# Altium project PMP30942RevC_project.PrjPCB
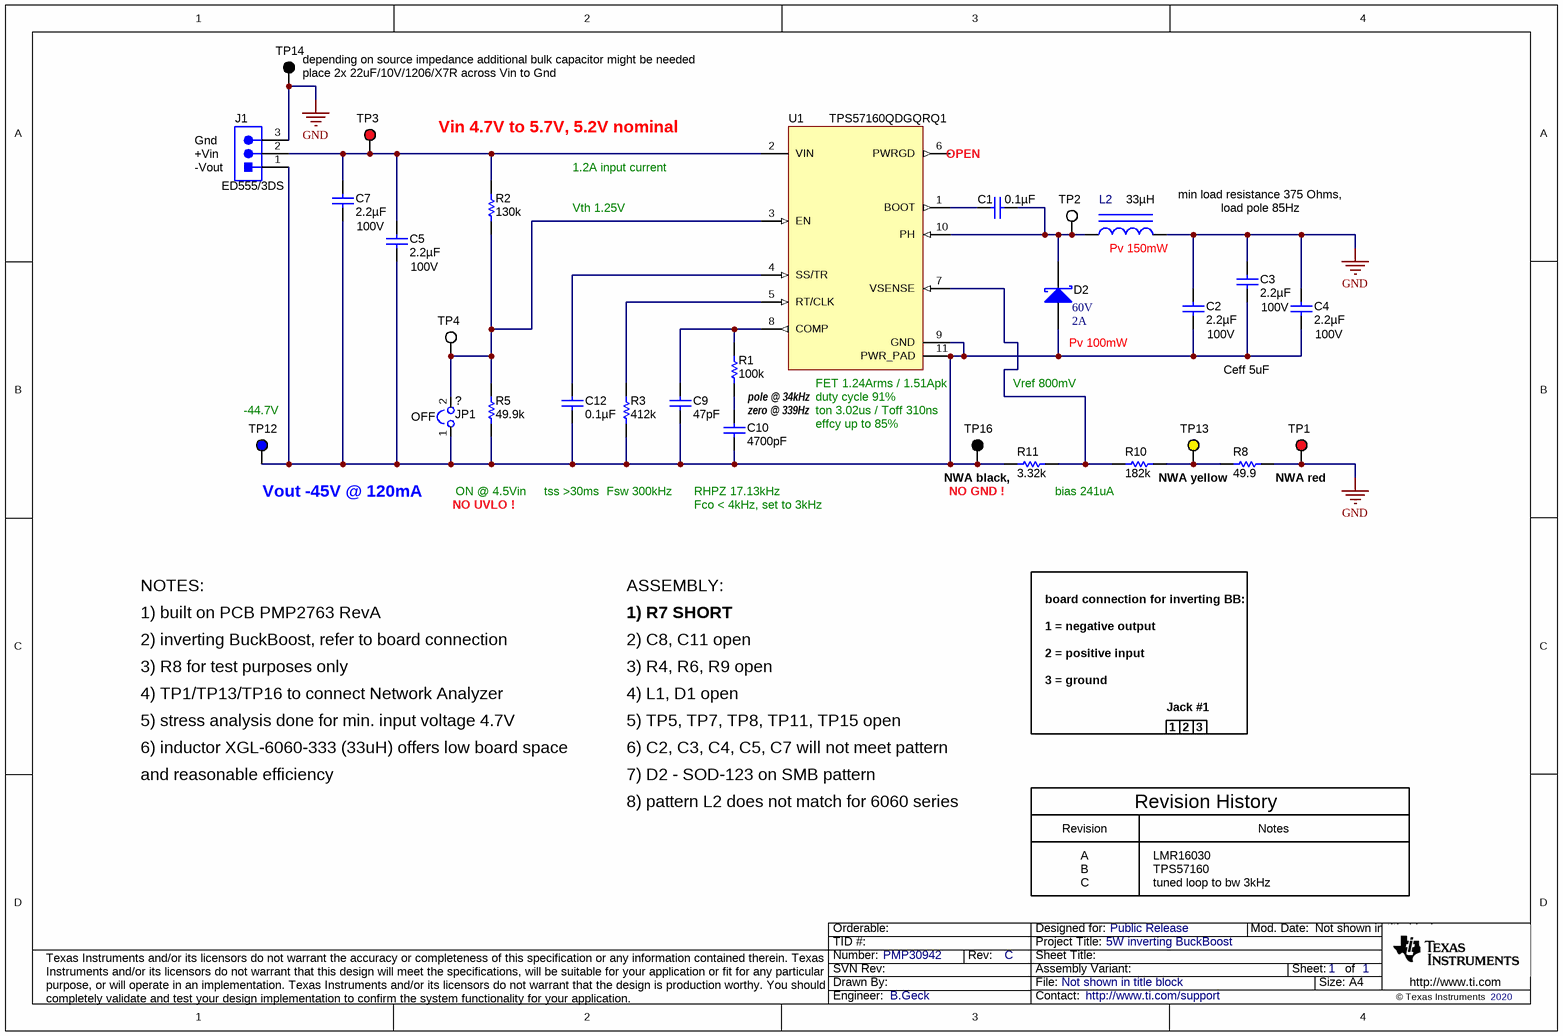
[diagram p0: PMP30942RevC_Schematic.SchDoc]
CopyrightYear: 2020; PCB_Layout: B.Geck; PCB_Rev: A; PRJ_Customer: Public Release; PRJ_Engineer: B.Geck; PRJ_Number: PMP30942; PRJ_Title: 5W inverting BuckBoost; SCH_Rev: C; TechSupport: http://www.ti.com/support
1 sheet, 29 parts. Net scope: global (net labels, ports and power ports of the same name join across sheets).
Board file: PMP2763_REV_A_board.PcbDoc

## Sheet PMP30942RevC_Schematic.SchDoc
size A4; Date: Not shown in title block; ApprovedBy: Not shown in title block; CheckedBy: Not shown in title block; Author: Not shown in title block; CompanyName: Not shown in title block; Engineer: Not shown in title block; Organization: Not shown in title block; Address1: Not shown in title block; Address2: Not shown in title block; Address3: Not shown in title block; Address4: Not shown in title block; DocumentNumber: 1; Revision: Use project parameter SCH_Rev; SheetNumber: 1; SheetTotal: 1; PageSetup: Record=PageOptions¦CenterHorizontal=True¦CenterVertical=True¦PrintScale=0.70¦XCorrection=1.00¦YCorrection=1.00¦PrintKind=0¦BorderSize=5000000¦LeftOffset=0¦BottomOffset=0¦Orientation=2¦PaperLength=1000¦PaperWidth=1000¦Scale=100¦PaperSource=15¦PrintQuality=600¦MediaType=1¦DitherType=10¦PaperKind=A4¦PrintScaleMode=1

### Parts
?  JP1  [JMP-600_035MIL]
C1  ValueDisplayed: 0.1µF  [0603]  (hidden comment: GRM188R71E104KA01D)
C2  ValueDisplayed: 2.2µF  Value2: 100V  [1206_190]  (hidden comment: GRM31CR72A225KA73L)
C3  ValueDisplayed: 2.2µF  Value2: 100V  [1206_190]  (hidden comment: GRM31CR72A225KA73L)
C4  ValueDisplayed: 2.2µF  Value2: 100V  [1206_190]  (hidden comment: GRM31CR72A225KA73L)
C5  ValueDisplayed: 2.2µF  Value2: 100V  [1206_190]  (hidden comment: GRM31CR72A225KA73L)
C7  ValueDisplayed: 2.2µF  Value2: 100V  [1206_190]  (hidden comment: GRM31CR72A225KA73L)
C9  ValueDisplayed: 47pF  [0603]  (hidden comment: GRM1885C1H470JA01D)
C10  ValueDisplayed: 4700pF  [0603]  (hidden comment: GRM188R71E472KA01D)
C12  ValueDisplayed: 0.1µF  [0603]  (hidden comment: GRM188R71E104KA01D)
D2  value 60V  Value1: 2A  [SOD-123W]  (hidden comment: PMEG6020ER,115)
J1  ED555/3DS  [TERM_BLK_ED555-3DS]
L2  ValueDisplayed: 33µH  [XAL6060]  (hidden comment: XAL6060-333MEB)
R1  ValueDisplayed: 100k  [0603]  (hidden comment: CRCW0603100KFKEA)
R2  ValueDisplayed: 130k  [0603]  (hidden comment: CRCW0603130KFKEA)
R3  ValueDisplayed: 412k  [0603]  (hidden comment: CRCW0603412KFKEA)
R5  ValueDisplayed: 49.9k  [0603]  (hidden comment: CRCW060349K9FKEA)
R8  ValueDisplayed: 49.9  [0603]  (hidden comment: CRCW060349R9FKEA)
R10  ValueDisplayed: 182k  [0603]  (hidden comment: CRCW0603182KFKEA)
R11  ValueDisplayed: 3.32k  [0603]  (hidden comment: CRCW06033K32FKEA)
TP1  5000  [Keystone5000]  (value not drawn)
TP2  5002  [Keystone5002]  (value not drawn)
TP3  5000  [Keystone5000]  (value not drawn)
TP4  5002  [Keystone5002]  (value not drawn)
TP12  5117  [Keystone5117]  (value not drawn)
TP13  5004  [Keystone5004]  (value not drawn)
TP14  5001  [Keystone5001]  (value not drawn)
TP16  5001  [Keystone5001]  (value not drawn)
U1  TPS57160QDGQRQ1  [DGQ0010D_N]

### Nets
GND: C2.1 C3.1 C4.1 J1.3 L2.2 R8.2 TP1.1 TP14.1
Net?_1: ?.1 C2.2 C3.2 C4.2 C5.2 C7.2 C9.2 C10.2 C12.2 D2.2(A) J1.1 R3.1 R5.1 R11.1 TP12.1 TP16.1 U1.9(GND) U1.11(PWR_PAD)
Net?_2: ?.2 R2.1 R5.2 TP4.1 U1.3(EN)
NetC1_1: C1.1 U1.1(BOOT)
NetC1_2: C1.2 D2.1(K) L2.1 TP2.1 U1.10(PH)
NetC5_1: C5.1 C7.1 J1.2 R2.2 TP3.1 U1.2(VIN)
NetC9_1: C9.1 R1.2 U1.8(COMP)
NetC10_1: C10.1 R1.1
NetC12_1: C12.1 U1.4(SS/TR)
NetR3_2: R3.2 U1.5(RT/CLK)
NetR8_1: R8.1 R10.2 TP13.1
NetR10_1: R10.1 R11.2 U1.7(VSENSE)

Not connected (* = marked no-connect by the designer): U1 6(PWRGD)

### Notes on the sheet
- (near TP14) place 2x 22uF/10V/1206/X7R across Vin to Gnd
- (near TP14) depending on source impedance additional bulk capacitor might be needed
- (near J1) Gnd
- (near J1) +Vin
- (near J1) -Vout
- Vin 4.7V to 5.7V, 5.2V nominal
- 1.2A input current
- (near U1) OPEN
- Vth 1.25V
- (near L2) Pv 150mW
- (near L2) min load resistance 375 Ohms,
- load pole 85Hz
- (near U1) FET 1.24Arms / 1.51Apk
- Vref 800mV
- (near D2) Pv 100mW
- Ceff 5uF
- (near TP12) -44.7V
- (near ?) OFF
- pole @ 34kHz
- zero @ 339Hz
- (near U1) duty cycle 91%
- ton 3.02us / Toff 310ns
- effcy up to 85%
- (near TP12) Vout -45V @ 120mA
- NO UVLO !
- ON @ 4.5Vin
- tss >30ms
- Fsw 300kHz
- (near C10) RHPZ 17.13kHz
- Fco < 4kHz, set to 3kHz
- NO GND !
- NWA black,
- bias 241uA
- NWA yellow
- NWA red
- NOTES:
- ASSEMBLY:
- 1) built on PCB PMP2763 RevA
- 2) inverting BuckBoost, refer to board connection
- 2) C8, C11 open
- 1) R7 SHORT
- board connection for inverting BB:
- 1 = negative output
- 2 = positive input
- 3) R8 for test purposes only
- 4) TP1/TP13/TP16 to connect Network Analyzer
- 5) stress analysis done for min. input voltage 4.7V
- 4) L1, D1 open
- 3) R4, R6, R9 open
- 5) TP5, TP7, TP8, TP11, TP15 open
- 3 = ground
- Jack #1
- 6) inductor XGL-6060-333 (33uH) offers low board space
- and reasonable efficiency
- 6) C2, C3, C4, C5, C7 will not meet pattern
- 7) D2 - SOD-123 on SMB pattern
- 1
- 2
- 3
- 8) pattern L2 does not match for 6060 series
- Revision
- A
- LMR16030
- Revision History
- Notes
- B
- C
- TPS57160
- tuned loop to bw 3kHz

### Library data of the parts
? = JMP-600_035MIL: Jumper,  0.600 inch length, PVC Insulation, AWG 22,; Manufacturer: 3M; PartNumber: 923345-06-C; area: 70000; Value: 923345-06-C
C1 C12 = GRM188R71E104KA01D: CAP, CERM, 0.1 µF, 25 V, +/- 10%, X7R, 0603; Manufacturer: MuRata; Polarized: N; CompType: Capacitor; Value: 0.1uF; U/M: EA; Cap_F: 0.0000001; Tolerance_%: 10; Value1: Unknown; VDC_V: 25; Value2: 25V; TaMin_C: -55; TaMax_C: 125
C2-C5 C7 = GRM31CR72A225KA73L: CAP, CERM, 2.2 µF, 100 V,+/- 10%, X7R, 1206; Manufacturer: MuRata; Polarized: N; CompType: Capacitor; Value: 2.2uF; U/M: EA; Cap_F: 0.0000022; Tolerance_%: 10; VDC_V: 100; TaMin_C: -55; TaMax_C: 125; Cap_Case: 1206; SizeArea_mm2: 5.12; SizeAreaWB_mm2: 10.92; SizeX_mm: 3.2; SizeY_mm: 1.6; SizeZ_mm: 1.9; AEC Category: Q200; Green_Lifecycle: Active; Green_REACh: Passed
C9 = GRM1885C1H470JA01D: CAP, CERM, 47 pF, 50 V,+/- 5%, C0G/NP0, 0603; Manufacturer: MuRata; Polarized: N; CompType: Capacitor; Value: 47pF; U/M: EA; Cap_F: 0.000000000047; Tolerance_%: 5; VDC_V: 50; Value2: 50V; TaMin_C: -55; TaMax_C: 125; SizeArea_mm2: 1.28; SizeAreaWB_mm2: 4.68; SizeX_mm: 1.6; SizeY_mm: 0.8; SizeZ_mm: 1; AEC Category: Q200; Green_Lifecycle: Active; Green_REACh: Passed
C10 = GRM188R71E472KA01D: CAP, CERM, 4700 pF, 25 V,+/- 10%, X7R, 0603; Manufacturer: MuRata; Polarized: N; CompType: Capacitor; Value: 4700pF; U/M: EA; Cap_F: 0.0000000047; Tolerance_%: 10; VDC_V: 25; Value2: 25V; TaMin_C: -55; TaMax_C: 125; SizeArea_mm2: 1.28; SizeAreaWB_mm2: 4.68; SizeX_mm: 1.6; SizeY_mm: 0.8; SizeZ_mm: 1; AEC Category: Q200
D2 = PMEG6020ER,115: Diode, Schottky, 60 V, 2 A, SOD-123W; Manufacturer: Nexperia; U/M: EA; Vf_V: 0.53; Value2: 0.53V; Io_A: 2; Vr_V: 60; TJmax_C: 150; SizeAreaWB_mm2: 12.15; SizeArea_mm2: 5.95; SizeX_mm: 3.5; SizeY_mm: 1.7; SizeZ_mm: 1; AEC Category: Q101; Green_Lifecycle: Not Set; Green_REACh: Incomplete
J1 = ED555/3DS: Terminal Block, 6A, 3.5mm Pitch, 3-Pos, TH; Manufacturer: On-Shore Technology; SymbolCreator: a0799628; CompType: Connector; U/M: EA
L2 = CMP-0085398-2: Inductor, Shielded, Composite, 33 µH, 3.6 A, 0.105 ohm, AEC-Q200 Grade 1, SMD; Manufacturer: Coilcraft; Isat: 3.7A @ 30% inductance drop; AEC Qualified: Y; Green_Lifecycle: Not Set; SizeX_mm: 6.36; SizeAreaWB_mm2: 71.5616; AEC Category: Q200; Value: 33uH; SizeY_mm: 6.56; AEC Grade: 1; SizeZ_mm: 6.1; Green_REACh: Incomplete; DCR_ohm: 0.105; Value2: 3.6A; Irms: 3.6A @ 40C rise; SizeArea_mm2: 41.7216
R1 = CRCW0603100KFKEA: RES, 100 k, 1%, 0.1 W, 0603; Manufacturer: Vishay-Dale; CompType: Resistor; Value: 100k; Res_ohm: 100000; Tolerance_%: 1; Power_W: 0.1; Value2: 0.1W; VDC_V: 75; TempCo: 100 ppm/C; SizeArea_mm2: 1.28; SizeX_mm: 1.6; SizeY_mm: 0.8; EIA_Code: E96; U/M: EA; AEC Category: Q200; Green_Lifecycle: Active; Green_REACh: Passed
R2 = CRCW0603130KFKEA: RES, 130 k, 1%, 0.1 W, 0603; Manufacturer: Vishay-Dale; CompType: Resistor; Value: 130k; Res_ohm: 130000; Tolerance_%: 1; Power_W: 0.1; Value2: 0.1W; VDC_V: 75; TempCo: 100 ppm/C; SizeArea_mm2: 1.28; SizeX_mm: 1.6; SizeY_mm: 0.8; EIA_Code: E96; U/M: EA; AEC Category: Q200; Green_Lifecycle: Active; Green_REACh: Passed
R3 = CRCW0603412KFKEA: RES, 412 k, 1%, 0.1 W, 0603; Manufacturer: Vishay-Dale; CompType: Resistor; Value: 412k; Res_ohm: 412000; Tolerance_%: 1; Power_W: 0.1; Value2: 0.1W; VDC_V: 75; TempCo: 100 ppm/C; SizeArea_mm2: 1.28; SizeX_mm: 1.6; SizeY_mm: 0.8; EIA_Code: E96; U/M: EA; AEC Category: Q200
R5 = CRCW060349K9FKEA: RES, 49.9 k, 1%, 0.1 W, 0603; Manufacturer: Vishay-Dale; CompType: Resistor; Value: 49.9k; Res_ohm: 49900; Value_Code: 49k9; Tolerance_%: 1; Power_W: 0.1; Value2: 0.1W; VDC_V: 75; TempCo: 100 ppm/C; EIA_Code: E96; U/M: EA
R8 = CRCW060349R9FKEA: RES, 49.9, 1%, 0.1 W, 0603; Manufacturer: Vishay-Dale; CompType: Resistor; Value: 49.9; Value_Code: 49R9; Tolerance_%: 1; Power_W: 0.1; Value2: 0.1W; VDC_V: 75; TempCo: 100 ppm/C; EIA_Code: E96; U/M: EA
R10 = CRCW0603182KFKEA: RES, 182 k, 1%, 0.1 W, 0603; Manufacturer: Vishay-Dale; CompType: Resistor; Value: 182k; Res_ohm: 182000; Tolerance_%: 1; Power_W: 0.1; Value2: 0.1W; VDC_V: 75; TempCo: 100 ppm/C; SizeArea_mm2: 1.28; SizeX_mm: 1.6; SizeY_mm: 0.8; EIA_Code: E96; U/M: EA; AEC Category: Q200; Green_Lifecycle: Active; Green_REACh: Passed
R11 = CRCW06033K32FKEA: RES, 3.32 k, 1%, 0.1 W, 0603; Manufacturer: Vishay-Dale; CompType: Resistor; Value: 3.32k; Res_ohm: 3320; Value_Code: 3k32; Tolerance_%: 1; Power_W: 0.1; Value2: 0.1W; VDC_V: 75; TempCo: 100 ppm/C; SizeArea_mm2: 1.28; SizeX_mm: 1.6; SizeY_mm: 0.8; EIA_Code: E96; U/M: EA; AEC Category: Q200; Green_Lifecycle: Active; Green_REACh: Passed
TP1 TP3 = 5000: Test Point, Miniature, Red, TH; Manufacturer: Keystone; CompType: Test Point Loop; U/M: EA
TP2 TP4 = 5002: Test Point, Miniature, White, TH; Manufacturer: Keystone; CompType: Test Point Loop; U/M: EA
TP12 = 5117: Test Point, Miniature, Blue, TH; Manufacturer: Keystone; CompType: Test Point Loop; U/M: EA
TP13 = 5004: Test Point, Miniature, Yellow, TH; Manufacturer: Keystone; CompType: Test Point Loop; U/M: EA
TP14 TP16 = 5001: Test Point, Miniature, Black, TH; Manufacturer: Keystone; CompType: Test Point Loop; U/M: EA
U1 = TPS54040ADGQ: 1.5 A, 60 V Step Down DC/DC Converter with Eco-mode, DGQ0010D; Manufacturer: Texas Instruments; SymbolCreator: a0411947; CompType: IC; U/M: EA

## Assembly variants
001: all parts fitted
